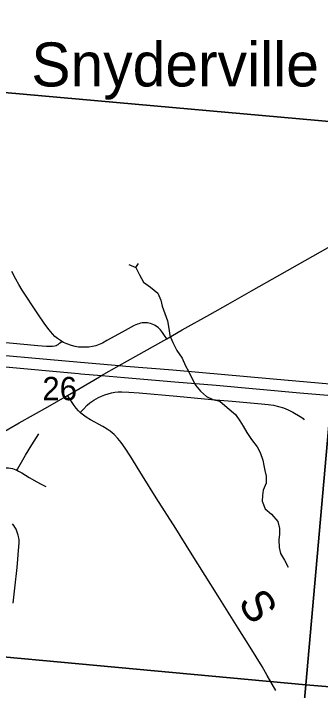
# Model space of a CAD drawing. Extents: x 831 to 1552, y 430 to 870.
# Drawn here: x 1352.96 to 1363.98, y 678.59 to 702.9 of the extents above; entities that cross this region are included whole.
import ezdxf

# ---------------------------------------------------------------- set-up
doc = ezdxf.new("R2010")
doc.units = 0
for name, color, linetype in [('GM_X_Corporation', 7, 'Continuous'), ('GM_X_County_Road', 7, 'Continuous'), ('GM_X_County_Road_Text', 7, 'Continuous'), ('GM_X_Interstate_Route', 7, 'Continuous'), ('GM_X_Minor_River', 7, 'Continuous'), ('GM_X_Section_Text', 7, 'Continuous'), ('GM_X_Township_Road', 7, 'Continuous'), ('GM_X_Unincorporated_Text', 7, 'Continuous')]:
    doc.layers.add(name, color=color, linetype=linetype)

msp = doc.modelspace()

# ---------------------------------------------------------------- linework, layer by layer
at = {"layer": 'GM_X_Corporation'}
for points in [[(1347.89, 720.702), (1366.951, 719.126), (1365.244, 698.931), (1346.049, 700.645)], [(1346.049, 700.645), (1365.244, 698.931), (1363.462, 678.79), (1343.776, 680.603)], [(1365.244, 698.931), (1385.781, 697.271), (1383.627, 677.106), (1363.462, 678.79)], [(1343.776, 680.603), (1363.462, 678.79), (1361.646, 658.883), (1342.018, 660.52), (1341.746, 660.547)], [(1363.462, 678.79), (1383.627, 677.106), (1381.941, 657.229), (1361.881, 658.872), (1361.646, 658.883)]]:
    msp.add_lwpolyline(points, close=True, dxfattribs=at)
at = {"layer": 'GM_X_County_Road'}
for points in [[(1358.462, 691.217), (1359.016, 691.539), (1360.01, 692.09), (1360.667, 692.459), (1361.512, 692.939), (1362.529, 693.516), (1365.804, 695.368)], [(1354.905, 689.182), (1355.358, 689.441), (1356.049, 689.856), (1356.125, 689.9), (1356.754, 690.257), (1357.352, 690.597), (1358.359, 691.157), (1358.462, 691.217)], [(1350.474, 686.674), (1350.626, 686.759), (1351.385, 687.184), (1352.413, 687.764), (1353.169, 688.195), (1354.196, 688.777), (1354.905, 689.182)], [(1355.354, 688.57), (1355.289, 688.635), (1355.209, 688.728), (1355.135, 688.827), (1355.001, 689.035), (1354.905, 689.182)], [(1362.377, 678.584), (1362.076, 679.127), (1361.889, 679.45), (1361.464, 680.137), (1361.034, 680.821), (1360.307, 681.978), (1359.841, 682.713), (1359.313, 683.555), (1358.786, 684.398), (1358.09, 685.502), (1357.597, 686.292), (1357.17, 686.978), (1356.968, 687.292), (1356.823, 687.495), (1356.703, 687.64), (1356.571, 687.774), (1356.429, 687.897), (1356.328, 687.971), (1356.169, 688.072), (1355.731, 688.306), (1355.571, 688.401), (1355.471, 688.471), (1355.376, 688.549), (1355.354, 688.57)]]:
    msp.add_lwpolyline(points, dxfattribs=at)
at = {"layer": 'GM_X_Interstate_Route'}
for points in [[(1331.945, 686.879), (1334.348, 687.724), (1336.811, 688.586), (1339.389, 689.495), (1340.328, 689.819), (1340.919, 690.009), (1341.454, 690.169), (1341.993, 690.315), (1342.415, 690.418), (1342.961, 690.537), (1343.571, 690.654), (1344.06, 690.737), (1344.552, 690.807), (1345.107, 690.872), (1345.663, 690.924), (1346.158, 690.96), (1346.654, 690.983), (1347.213, 690.996), (1347.709, 690.995), (1348.268, 690.98), (1348.81, 690.952), (1349.484, 690.9), (1351.054, 690.763), (1355.364, 690.381)], [(1352.541, 690.224), (1355.298, 689.97), (1355.378, 689.964)], [(1355.364, 690.381), (1356.754, 690.257), (1356.994, 690.236), (1358.681, 690.097), (1362.281, 689.777), (1363.508, 689.669), (1365.413, 689.506)], [(1355.378, 689.964), (1356.125, 689.9), (1356.943, 689.83), (1358.757, 689.674), (1360.242, 689.546), (1363.249, 689.278), (1365.391, 689.094)]]:
    msp.add_lwpolyline(points, dxfattribs=at)
at = {"layer": 'GM_X_Minor_River'}
for points in [[(1357.107, 693.888), (1357.356, 693.772), (1357.489, 693.512), (1357.631, 693.252), (1357.879, 693.074), (1358.15, 692.851), (1358.253, 692.599), (1358.296, 692.386), (1358.399, 692.127), (1358.495, 691.867), (1358.537, 691.586), (1358.579, 691.335), (1358.683, 691.083), (1358.823, 690.801), (1359.018, 690.525), (1359.143, 690.25), (1359.247, 690.059), (1359.373, 689.784), (1359.499, 689.555), (1359.671, 689.333), (1359.889, 689.14), (1360.124, 689.039), (1360.366, 688.975), (1360.637, 688.752), (1360.93, 688.498), (1361.094, 688.268), (1361.206, 688.077), (1361.34, 687.855), (1361.504, 687.603), (1361.706, 687.342), (1361.825, 687.128), (1361.92, 686.861), (1361.948, 686.671), (1361.991, 686.481), (1362.034, 686.283), (1362.031, 686.032), (1361.93, 685.783), (1361.897, 685.593), (1361.894, 685.388), (1361.997, 685.114), (1362.23, 684.914), (1362.455, 684.653), (1362.513, 684.409), (1362.51, 684.204), (1362.493, 683.992), (1362.497, 683.718), (1362.547, 683.505), (1362.696, 683.261), (1362.822, 683.016)], [(1357.356, 693.772), (1357.448, 693.922)]]:
    msp.add_lwpolyline(points, dxfattribs=at)
at = {"layer": 'GM_X_Township_Road'}
for points in [[(1353.835, 692.118), (1353.813, 692.151), (1353.274, 692.968), (1353.152, 693.162), (1353.041, 693.36), (1352.9, 693.637)], [(1354.695, 691.123), (1354.647, 691.15), (1354.543, 691.222), (1354.446, 691.302), (1354.357, 691.391), (1354.237, 691.535), (1354.09, 691.738), (1353.835, 692.118)], [(1358.462, 691.217), (1358.382, 691.338), (1358.314, 691.442), (1358.277, 691.491), (1358.238, 691.537), (1358.196, 691.581), (1358.151, 691.622), (1358.102, 691.659), (1358.051, 691.691), (1357.998, 691.72), (1357.942, 691.745), (1357.885, 691.764), (1357.826, 691.779), (1357.767, 691.788), (1357.706, 691.792), (1357.646, 691.792), (1357.585, 691.786), (1357.526, 691.775), (1357.467, 691.76), (1357.409, 691.741), (1357.297, 691.692), (1356.861, 691.456), (1356.318, 691.151), (1356.151, 691.065), (1355.979, 690.989), (1355.92, 690.968), (1355.797, 690.938), (1355.672, 690.92), (1355.547, 690.912), (1355.421, 690.912), (1355.379, 690.915)], [(1352.289, 691.116), (1353.463, 691.013), (1353.835, 690.978), (1354.145, 690.956), (1354.297, 690.948), (1354.363, 690.951), (1354.44, 690.963), (1354.494, 690.978), (1354.53, 690.995), (1354.562, 691.016), (1354.613, 691.055), (1354.651, 691.087), (1354.695, 691.123)], [(1355.379, 690.915), (1355.295, 690.921), (1355.171, 690.942), (1355.049, 690.974), (1354.872, 691.037), (1354.757, 691.089), (1354.695, 691.123)], [(1355.354, 688.57), (1355.473, 688.693), (1355.604, 688.828), (1355.697, 688.912), (1355.851, 689.017), (1356.013, 689.109), (1356.125, 689.162), (1356.241, 689.207), (1356.359, 689.246), (1356.479, 689.277), (1356.601, 689.298), (1356.725, 689.31), (1356.849, 689.312), (1357.097, 689.301), (1357.468, 689.27), (1358.83, 689.151), (1360.067, 689.041), (1360.81, 688.98), (1361.862, 688.886), (1362.109, 688.861), (1362.293, 688.832), (1362.475, 688.791), (1362.652, 688.735), (1362.825, 688.665), (1362.991, 688.581), (1363.259, 688.425), (1363.312, 688.392), (1363.361, 688.355), (1363.403, 688.309)], [(1353.082, 686.496), (1353.103, 686.533), (1353.396, 687.041), (1353.614, 687.407), (1353.788, 687.667), (1353.872, 687.8)], [(1350.976, 685.739), (1351.052, 685.784), (1351.484, 686.028), (1351.862, 686.241), (1352.187, 686.418), (1352.355, 686.498), (1352.473, 686.543), (1352.534, 686.56), (1352.596, 686.573), (1352.66, 686.58), (1352.723, 686.583), (1352.787, 686.579), (1352.85, 686.57), (1352.92, 686.554), (1352.987, 686.535), (1353.048, 686.512), (1353.082, 686.496)], [(1353.082, 686.496), (1353.145, 686.462), (1353.254, 686.401), (1353.518, 686.241), (1353.802, 686.081), (1353.952, 685.999), (1354.127, 685.906)], [(1352.954, 681.726), (1353.008, 682.264), (1353.088, 683.007), (1353.157, 683.755), (1353.164, 683.894), (1353.159, 684.002), (1353.149, 684.066), (1353.128, 684.17), (1353.108, 684.233), (1353.081, 684.304), (1353.053, 684.379), (1353.013, 684.453), (1352.972, 684.512), (1352.924, 684.572)]]:
    msp.add_lwpolyline(points, dxfattribs=at)

# ---------------------------------------------------------------- texts
at = {"layer": 'GM_X_County_Road_Text'}
msp.add_text('S', height=1.136, rotation=302.6588, dxfattribs=at).set_placement((1360.997, 681.75))
at = {"layer": 'GM_X_Section_Text'}
msp.add_text('26', height=0.8371, rotation=0, dxfattribs=at).set_placement((1353.996, 689.01))
at = {"layer": 'GM_X_Unincorporated_Text'}
msp.add_text('Snyderville', height=1.57955, rotation=0, dxfattribs=at).set_placement((1353.6, 700.28))

doc.saveas('drawing.dxf')
